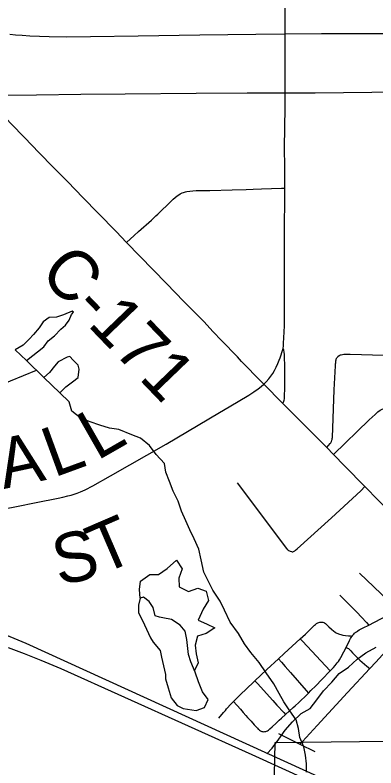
# Model space of a CAD drawing. Extents: x 0 to 34, y 0 to 22.
# Drawn here: x 14.741 to 15.153, y 10.267 to 11.126 of the extents above; entities that cross this region are included whole.
import ezdxf

# ---------------------------------------------------------------- set-up
doc = ezdxf.new("R2010")
doc.units = 0
for name, color, linetype in [('GM_X_Corporation', 7, 'Continuous'), ('GM_X_County_Road', 7, 'Continuous'), ('GM_X_County_Road_Text', 7, 'Continuous'), ('GM_X_Minor_Lake', 7, 'Continuous'), ('GM_X_Minor_River', 7, 'Continuous'), ('GM_X_Rail_Line', 7, 'Continuous'), ('GM_X_State_Route', 7, 'Continuous'), ('GM_X_Township_Road', 7, 'Continuous')]:
    doc.layers.add(name, color=color, linetype=linetype)

msp = doc.modelspace()

# ---------------------------------------------------------------- linework, layer by layer
at = {"layer": 'GM_X_Corporation'}
msp.add_lwpolyline([(15.84951, 11.25481), (15.5254, 11.25372), (15.5253, 11.11224), (15.5253, 11.10823), (15.52552, 11.04302), (15.54303, 11.04315), (15.55107, 11.04318), (15.54409, 10.64231), (15.59439, 10.64042), (15.58053, 10.35329), (15.60577, 10.35275), (15.60263, 10.2988), (15.42412, 10.30006), (15.03767, 10.29546), (15.03553, 10.18698), (15.00218, 10.17457), (14.97601, 10.15645), (14.96043, 10.13223), (14.95656, 10.09468), (14.95687, 10.06434), (15.02805, 10.06297), (15.03356, 9.98888), (15.03025, 9.92143), (17.2525, 9.92143)], dxfattribs=at)
at = {"layer": 'GM_X_County_Road'}
for p, q in [((15.04959, 11.0224), (15.04952, 11.03718)), ((15.04661, 10.68311), (15.02523, 10.70487)), ((15.10469, 10.62458), (15.09701, 10.63231))]:
    msp.add_line(p, q, dxfattribs=at)
for points in [[(15.04975, 11.10463), (15.05012, 11.17068)], [(15.04952, 11.03718), (15.04953, 11.05937), (15.04963, 11.07606), (15.04977, 11.08595), (15.04975, 11.10463)], [(14.70518, 11.03453), (14.72373, 11.03468), (14.76579, 11.03501), (14.81625, 11.03572), (14.86683, 11.03607), (14.94788, 11.03677), (15.00635, 11.03723), (15.04952, 11.03718)], [(15.04952, 11.03718), (15.08395, 11.03744), (15.14863, 11.03821), (15.22937, 11.03923), (15.24731, 11.0394)], [(14.86855, 10.86634), (14.85645, 10.87901), (14.83608, 10.89997), (14.81869, 10.91775), (14.80135, 10.93556), (14.78481, 10.9524), (14.76881, 10.96893), (14.75183, 10.98624), (14.73678, 11.00191), (14.72046, 11.019), (14.70518, 11.03453)], [(15.0491, 10.9286), (15.04909, 10.94491), (15.04906, 10.95261), (15.0489, 10.97455), (15.0496, 11.02043), (15.04959, 11.0224)], [(15.04717, 10.74562), (15.04754, 10.74852), (15.04784, 10.75175), (15.0482, 10.75757), (15.04846, 10.76448), (15.04865, 10.77119), (15.04868, 10.79809), (15.04901, 10.87145), (15.0491, 10.9286)], [(14.96754, 10.76463), (14.95666, 10.77615), (14.93397, 10.7992), (14.91392, 10.81959), (14.86855, 10.86634)], [(14.99505, 10.7358), (14.97706, 10.75455), (14.96754, 10.76463)], [(15.03327, 10.71387), (15.03543, 10.71713), (15.03739, 10.72027), (15.03934, 10.72407), (15.04129, 10.72846), (15.04287, 10.73205), (15.04402, 10.73501), (15.04509, 10.7382), (15.04597, 10.7411), (15.04717, 10.74562)], [(15.04661, 10.68311), (15.04751, 10.68433), (15.04801, 10.68526), (15.0485, 10.68659), (15.04874, 10.68799), (15.04889, 10.69004), (15.04908, 10.70123), (15.04925, 10.72253), (15.04894, 10.73877), (15.04858, 10.74142), (15.04798, 10.74369), (15.04717, 10.74562)], [(15.02523, 10.70487), (15.02247, 10.70761), (14.99989, 10.73075), (14.99505, 10.7358)], [(15.02523, 10.70487), (15.02795, 10.70747), (15.03087, 10.71083), (15.03327, 10.71387)], [(14.9857, 10.67891), (15.00812, 10.69212), (15.01394, 10.69587), (15.01883, 10.69934), (15.02219, 10.70205), (15.02523, 10.70487)], [(15.09701, 10.63231), (15.06581, 10.66373), (15.05607, 10.67348), (15.04661, 10.68311)], [(14.85013, 10.60002), (14.91357, 10.63624), (14.9745, 10.67231), (14.9857, 10.67891)], [(15.14074, 10.58779), (15.11779, 10.61125), (15.10469, 10.62458)], [(14.65895, 10.54137), (14.65999, 10.54195), (14.66282, 10.54358), (14.66869, 10.54654), (14.67388, 10.54895), (14.6805, 10.55146), (14.68962, 10.55442), (14.69991, 10.5569), (14.70756, 10.55848), (14.71708, 10.56025), (14.74273, 10.56507), (14.76529, 10.56956), (14.79042, 10.5747), (14.79587, 10.57591), (14.80131, 10.57719), (14.8052, 10.57824), (14.80865, 10.57933), (14.812, 10.58051), (14.81572, 10.58194), (14.82114, 10.58421), (14.83014, 10.58862), (14.85013, 10.60002)], [(15.19086, 10.53692), (15.18482, 10.54296), (15.15604, 10.57216), (15.14074, 10.58779)]]:
    msp.add_lwpolyline(points, dxfattribs=at)
at = {"layer": 'GM_X_Minor_Lake'}
for p, q in [((14.74116, 10.74412), (14.7541, 10.73164)), ((14.77403, 10.71241), (14.79218, 10.69489)), ((14.90821, 10.39325), (14.91291, 10.37319))]:
    msp.add_line(p, q, dxfattribs=at)
for points in [[(14.7541, 10.73164), (14.7739, 10.74753), (14.77914, 10.75439), (14.78629, 10.76013), (14.79342, 10.76739), (14.79869, 10.77198), (14.8028, 10.7777), (14.80578, 10.78417), (14.80803, 10.78684), (14.80651, 10.78797), (14.79632, 10.7841), (14.78839, 10.78138), (14.78007, 10.78094), (14.7733, 10.77596), (14.76881, 10.7691), (14.76206, 10.76146), (14.75718, 10.75612), (14.75042, 10.74924), (14.74116, 10.74412)], [(14.79218, 10.69489), (14.79927, 10.70168), (14.8068, 10.70743), (14.81319, 10.71241), (14.81425, 10.72189), (14.81308, 10.72644), (14.80736, 10.73208), (14.80354, 10.73622), (14.80052, 10.73544), (14.79034, 10.73043), (14.78622, 10.72547), (14.7806, 10.71822), (14.77403, 10.71241)], [(14.91291, 10.37319), (14.91295, 10.36826), (14.91605, 10.35804), (14.91955, 10.34669), (14.92643, 10.33802), (14.93326, 10.33466), (14.94804, 10.33212), (14.95748, 10.33561), (14.96157, 10.34474), (14.95507, 10.35341), (14.95044, 10.36513), (14.94695, 10.37611), (14.94193, 10.38782), (14.93922, 10.39615), (14.9372, 10.4132), (14.93523, 10.42266), (14.92988, 10.42983), (14.91961, 10.4362), (14.90975, 10.43802), (14.90596, 10.43875), (14.90103, 10.44022), (14.89869, 10.44969), (14.89447, 10.45686), (14.88799, 10.46174), (14.88384, 10.46057), (14.88201, 10.45259), (14.88208, 10.44387), (14.88669, 10.43518), (14.89593, 10.41516), (14.89899, 10.41025), (14.90701, 10.40083), (14.90821, 10.39325)]]:
    msp.add_lwpolyline(points, dxfattribs=at)
at = {"layer": 'GM_X_Minor_River'}
for p, q in [((14.77403, 10.71241), (14.7541, 10.73164)), ((14.71167, 10.69892), (14.76552, 10.72061)), ((14.80299, 10.68445), (14.79218, 10.69489))]:
    msp.add_line(p, q, dxfattribs=at)
for points in [[(14.84902, 10.65447), (14.83802, 10.6578), (14.82701, 10.66188), (14.81677, 10.6656), (14.8061, 10.67386), (14.80299, 10.68445)], [(15.07387, 10.26179), (15.07379, 10.27127), (15.07296, 10.28112), (15.07099, 10.29097), (15.06637, 10.30155), (15.06477, 10.31178), (15.06205, 10.32162), (15.05478, 10.3318), (15.04789, 10.34199), (15.04289, 10.35181), (15.03675, 10.36276), (15.02795, 10.37521), (15.01991, 10.3869), (15.01036, 10.39859), (15.00309, 10.40839), (14.99619, 10.4201), (14.98662, 10.43292), (14.98046, 10.4469), (14.97546, 10.4571), (14.96704, 10.46955), (14.96204, 10.47937), (14.95666, 10.49033), (14.95352, 10.50434), (14.95115, 10.51646), (14.94576, 10.52817), (14.94076, 10.53837), (14.93614, 10.54858), (14.93114, 10.55991), (14.92726, 10.57126), (14.92188, 10.5826), (14.91763, 10.59356), (14.91338, 10.60415), (14.91179, 10.61437), (14.90224, 10.62454), (14.8946, 10.63472), (14.88431, 10.64298), (14.87444, 10.64708), (14.85963, 10.65303), (14.84902, 10.65447)], [(14.88384, 10.46057), (14.88339, 10.47043), (14.88445, 10.47992), (14.89499, 10.48758), (14.90483, 10.48766), (14.91499, 10.49418), (14.92552, 10.50375), (14.93203, 10.49394), (14.92833, 10.48329), (14.9284, 10.47343), (14.93904, 10.4682), (14.94999, 10.47208), (14.95948, 10.46836), (14.96221, 10.45776), (14.95585, 10.44785), (14.95027, 10.43529), (14.95977, 10.43119), (14.96926, 10.42672), (14.95947, 10.42019), (14.94966, 10.41708), (14.94671, 10.40682), (14.94792, 10.39697), (14.95027, 10.38675), (14.94614, 10.37799)], [(15.0285, 10.28273), (15.03467, 10.28917), (15.04254, 10.29947), (15.04965, 10.30977), (15.0579, 10.31931), (15.06767, 10.32887), (15.07822, 10.33464), (15.08571, 10.34455), (15.09321, 10.35485), (15.10297, 10.36478), (15.11122, 10.37433), (15.12176, 10.38161), (15.13191, 10.3908), (15.14169, 10.39808), (15.15338, 10.40461)]]:
    msp.add_lwpolyline(points, dxfattribs=at)
at = {"layer": 'GM_X_Rail_Line'}
for points in [[(14.14438, 10.38834), (14.32784, 10.41896), (14.52635, 10.44326), (14.5815, 10.446), (14.62524, 10.4446), (14.66175, 10.43975), (14.68994, 10.43246), (14.71471, 10.42512), (14.75351, 10.40922), (15.16476, 10.22148), (15.26799, 10.17069), (15.36132, 10.13068), (15.40374, 10.10624)], [(14.73322, 10.40403), (14.75158, 10.39726), (14.77058, 10.38954), (14.79344, 10.38036), (15.01163, 10.28197), (15.23877, 10.17861), (15.3042, 10.14945), (15.40395, 10.10569), (15.42614, 10.09599), (15.53569, 10.0484), (15.60735, 10.01741), (15.67424, 9.98912)]]:
    msp.add_lwpolyline(points, dxfattribs=at)
at = {"layer": 'GM_X_State_Route'}
msp.add_lwpolyline([(14.73506, 11.10423), (14.74151, 11.10365), (14.74921, 11.10307), (14.75821, 11.10255), (14.76911, 11.10208), (14.77993, 11.10173), (14.7998, 11.10139), (14.82713, 11.10148), (14.88181, 11.10233), (14.95204, 11.10361), (15.01625, 11.10443), (15.04975, 11.10463), (15.09109, 11.10488), (15.17085, 11.10519), (15.24482, 11.10551), (15.31754, 11.1059), (15.36291, 11.10624), (15.41574, 11.10672), (15.46174, 11.10714), (15.49991, 11.1074), (15.5255, 11.10768)], dxfattribs=at)
at = {"layer": 'GM_X_Township_Road'}
for points in [[(14.86855, 10.86634), (14.87704, 10.87443), (14.88202, 10.87895), (14.89679, 10.89215), (14.90186, 10.89677), (14.90415, 10.89889), (14.90739, 10.90179), (14.91633, 10.91045), (14.92184, 10.91584), (14.92386, 10.9177), (14.92623, 10.91971), (14.92804, 10.92104), (14.92987, 10.92214), (14.93193, 10.92311), (14.93359, 10.92372), (14.93588, 10.92437), (14.93743, 10.9247), (14.94073, 10.92516), (14.94399, 10.92548), (14.94782, 10.92566), (14.96351, 10.92593), (14.98898, 10.92652), (15.00512, 10.92702), (15.01319, 10.92735), (15.02249, 10.92768), (15.04528, 10.92847), (15.0491, 10.9286)], [(15.09701, 10.63231), (15.10102, 10.63701), (15.10168, 10.6379), (15.10203, 10.63842), (15.10254, 10.63945), (15.10298, 10.64069), (15.10322, 10.64177), (15.10336, 10.64275), (15.10345, 10.64389), (15.10548, 10.69829), (15.10703, 10.72566), (15.10719, 10.72798), (15.10727, 10.72901), (15.10741, 10.73049), (15.10753, 10.73151), (15.10767, 10.73243), (15.10795, 10.73353), (15.10827, 10.73425), (15.10863, 10.73495), (15.1092, 10.73574), (15.10989, 10.7365)], [(15.10989, 10.7365), (15.11122, 10.73751), (15.11286, 10.73824), (15.1135, 10.73844), (15.11506, 10.73876), (15.1164, 10.73889), (15.11862, 10.73898), (15.12397, 10.73898), (15.16224, 10.7378)], [(15.10469, 10.62458), (15.14534, 10.66391), (15.1522, 10.67033), (15.15556, 10.67315), (15.1582, 10.67495), (15.16051, 10.67622), (15.16229, 10.67702), (15.1636, 10.67747)], [(15.05713, 10.51342), (15.0558, 10.51366), (15.05477, 10.51402), (15.05393, 10.51455), (15.0527, 10.51565), (15.05135, 10.51721), (14.99529, 10.59232)], [(15.05713, 10.51342), (15.05826, 10.51353), (15.05913, 10.51374), (15.05985, 10.51403), (15.06074, 10.51459), (15.06152, 10.51519), (15.06336, 10.51676), (15.10265, 10.55205), (15.13585, 10.58299), (15.14074, 10.58779)], [(15.13464, 10.48906), (15.17568, 10.44993), (15.17709, 10.44858)], [(15.11215, 10.46378), (15.12154, 10.45437), (15.13157, 10.44432), (15.13692, 10.43877), (15.14264, 10.43261), (15.14501, 10.42984)], [(14.99076, 10.34271), (14.99857, 10.33379), (15.00176, 10.33009), (15.00482, 10.32648), (15.00665, 10.3244), (15.01062, 10.32007), (15.01418, 10.31601), (15.0172, 10.31269), (15.01781, 10.31206), (15.01878, 10.31113), (15.01958, 10.31043), (15.02044, 10.30974), (15.02147, 10.30909), (15.0228, 10.30842), (15.02419, 10.30814), (15.02542, 10.30806), (15.02635, 10.30812), (15.02745, 10.30833), (15.02838, 10.30863), (15.02923, 10.309), (15.03042, 10.3098), (15.0312, 10.31043), (15.03207, 10.31115), (15.03469, 10.31352), (15.0392, 10.31771), (15.04274, 10.32113), (15.04546, 10.32355), (15.04992, 10.32767), (15.05867, 10.33558), (15.06094, 10.33767), (15.06504, 10.34145), (15.07465, 10.35066), (15.07609, 10.3521), (15.07902, 10.35499), (15.08442, 10.36048), (15.0914, 10.36751), (15.10087, 10.3774), (15.10461, 10.38126), (15.1068, 10.38374), (15.10904, 10.38649), (15.11039, 10.38837), (15.11163, 10.39024), (15.11306, 10.3926), (15.11664, 10.39904), (15.11915, 10.40423), (15.12297, 10.41212), (15.12424, 10.41448), (15.12496, 10.41564), (15.12555, 10.41654), (15.12599, 10.41714), (15.12671, 10.41811), (15.12714, 10.41863), (15.12797, 10.41956), (15.12881, 10.42039), (15.12931, 10.42084), (15.12981, 10.42126), (15.13031, 10.42165), (15.13108, 10.42219), (15.13201, 10.42281), (15.13274, 10.42328), (15.13426, 10.42424), (15.13633, 10.42544), (15.13881, 10.42675), (15.14501, 10.42984), (15.16592, 10.44069)], [(14.97388, 10.32337), (14.97926, 10.32999), (14.98128, 10.33241), (14.98264, 10.33398), (14.98799, 10.33984), (14.98976, 10.3417), (14.99076, 10.34271), (14.99813, 10.35013), (15.01342, 10.36462), (15.0151, 10.36622), (15.02874, 10.37916), (15.04198, 10.39139), (15.04838, 10.39729), (15.06676, 10.41404), (15.0727, 10.41946), (15.08231, 10.42876), (15.08327, 10.42966), (15.08414, 10.43038), (15.08496, 10.43101), (15.08554, 10.4314), (15.08626, 10.43184), (15.08692, 10.43219), (15.08787, 10.43263), (15.0891, 10.43302), (15.08985, 10.43317), (15.09056, 10.43325), (15.09184, 10.43319), (15.09261, 10.43301), (15.0936, 10.43265), (15.09442, 10.43223), (15.09557, 10.43138), (15.0981, 10.42917), (15.09952, 10.42789), (15.10252, 10.42508), (15.10498, 10.42296), (15.10619, 10.42203), (15.10671, 10.42167), (15.10785, 10.42101), (15.10857, 10.42062), (15.10963, 10.42011), (15.11035, 10.41981), (15.1116, 10.41937), (15.11315, 10.41891), (15.11539, 10.41844), (15.11842, 10.41797), (15.12173, 10.41759), (15.12426, 10.41732), (15.12599, 10.41714)], [(15.06642, 10.29383), (15.06926, 10.29693), (15.08608, 10.31526), (15.12062, 10.35273), (15.14618, 10.38022), (15.15305, 10.3876), (15.16802, 10.40385), (15.17773, 10.41448)], [(15.06676, 10.41404), (15.06929, 10.41129), (15.10087, 10.3774)], [(15.11915, 10.40423), (15.12012, 10.40375), (15.12078, 10.40342), (15.12184, 10.40286), (15.12294, 10.40208), (15.12399, 10.40113), (15.1246, 10.4005), (15.12657, 10.39823), (15.12792, 10.39674), (15.12991, 10.3946), (15.13285, 10.39166), (15.13489, 10.38976), (15.14277, 10.38303), (15.14618, 10.38022)], [(15.04198, 10.39139), (15.0453, 10.38752), (15.04957, 10.38252), (15.05557, 10.3755), (15.07341, 10.35516), (15.07609, 10.3521)], [(15.0151, 10.36622), (15.01807, 10.36289), (15.03534, 10.34355), (15.03993, 10.33853), (15.04797, 10.32979), (15.04992, 10.32767)], [(15.04184, 10.30613), (15.0528, 10.30052), (15.05654, 10.29864), (15.06642, 10.29383), (15.08354, 10.2855)]]:
    msp.add_lwpolyline(points, dxfattribs=at)

# ---------------------------------------------------------------- texts
at = {"layer": 'GM_X_County_Road_Text'}
for s, height, rotation, p in [('C-171', 0.056818, 313.8476, (14.7673, 10.83022)), ('L', 0.05682, 29.8001, (14.83483, 10.61694)), ('L', 0.05682, 20.13301, (14.78544, 10.5979)), ('A', 0.05682, 12.10366, (14.72821, 10.585)), ('T', 0.05682, 23.31254, (14.83941, 10.4865)), ('S', 0.05682, 12.67517, (14.79107, 10.47453))]:
    msp.add_text(s, height=height, rotation=rotation, dxfattribs=at).set_placement(p)

doc.saveas('drawing.dxf')
